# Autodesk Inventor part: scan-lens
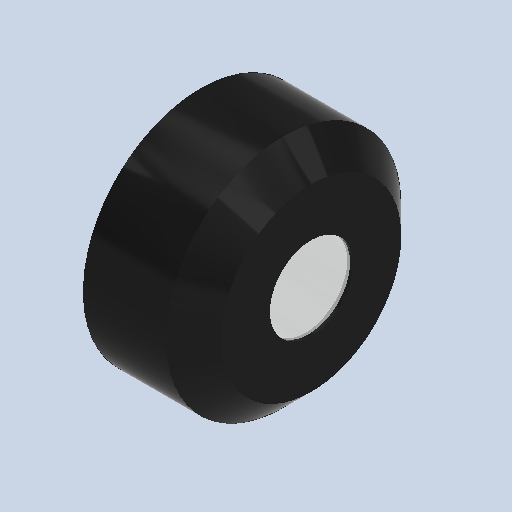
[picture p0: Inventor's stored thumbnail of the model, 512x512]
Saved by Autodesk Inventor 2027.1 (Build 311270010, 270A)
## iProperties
Created: 2026-07
Part Number: scan-lens
Material: Generic
Document SubType Name: Modeling
Designer: dunge
Density: 1 g/cm^3
Appearance: Default
Author: dunge
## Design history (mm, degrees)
derived "scan-lens-sl-simple.ipt"
  workaxis "Work Axis1"
  workpoint "Work Point1"
feature "Solid1::scan-lens-sl-simple.ipt"
tag "TaggingFeature1"
node "Finishes"
body "Solid1"
node "Finish1" dims "Finish1_Area" = 653.70617
node "Finish2" dims "Finish2_Area" = 72.96588
other parameters: "d4" = 0.508, "LIGHT_RADIUS" = 7.62, "d9" = 135 deg, "d10" = 0.508, "BODY_SIZE" = 20.32, "d12" = 5.08, "d13" = 0.508, "d14" = 0.508, "d15" = 0, "d16" = 0, "d18" = 21.59
